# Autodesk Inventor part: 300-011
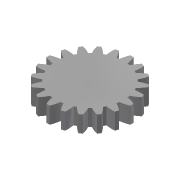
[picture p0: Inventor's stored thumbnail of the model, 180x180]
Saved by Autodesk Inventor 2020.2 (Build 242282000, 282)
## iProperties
Manager: www.cadconsulting.pl
Company: Fabian Stasiak CAD Consulting
CustomPartVersion: 1
Created: 2014-01
Part Number: 300-011
Material: Steel
Document SubType Name: Modeling
Designer: F.Stasiak
Categories: <?xml version="1.0" encoding="UTF-16"?> <MemberInstance><Categories><FamilyTemplate><FamilyTemplateParameter ValueType="xs:double" Id="1" ObjectReferenceKey="da
Density: 1 g/cm^3
Appearance: Stal
Author: F.Stasiak
Subject: Zbiór ćwiczeń. Autodesk Inventor 2020. Kurs podstawowy
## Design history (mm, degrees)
sketch "Sketch1"
  geometry: C1 r 25.433 at (0, 0)
  constraints: 1 centre point
  dimensions: "d0" = 50.86512 diameter of C1 (= da_da)
extrude "Extrusion1" new body sketch "Sketch1" distance "d1" = 10 (= da_b); taper "d2" = 0 deg
workplane "Work Plane2"
sketch "Sketch2"
  geometry: C1 r 25.433 at (0, 0) reference; C2 r 22.535 at (0, 0)
  constraints: 1 centre point, 1 coincident
  dimensions: "d3" = 45.07042 diameter of C2 (= da_dw)
feature "Średnica podziałowa" sketch "Sketch2" dims "d4" = 10, "d5" = 0
workplane "Work Plane8"
workplane "Work Plane9"
feature "Przekładnia walcowa" dims "da_b" = 10, "da_d" = 45, "da_aw" = 80, "da_da" = 50.86512, "da_df" = 40.74159, "da_dw" = 45.07042, angle "da_beta" = 0 deg, "da_lefttooth" = 0, "da_righttooth" = 0
body "Solid1"
body "Srf1"
other parameters: "d17" = 0, "d34" = 9 deg (computed from da_z), "d39" = 0, "d41" = 0, "d47" = 0, "d48" = 0
